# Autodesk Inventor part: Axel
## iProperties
Created: 2001-12
Part Number: Axel
Material: SS2172
Document SubType Name: Modeling
Designer: Tobben
Control State: 0
Master: False
Checked Out: False
Shininess: 64.0
Length Units: 11269
Angle Units: 11279
Time Units: 11290
Mass Units: 11283
Length Display Precision: 3
Angle Display Precision: 2
Density: 0.0
Volumn: 0.0
Area: 0.0
PropertySet Name: Model Information
Author: Tobben
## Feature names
1. Extrusion1
